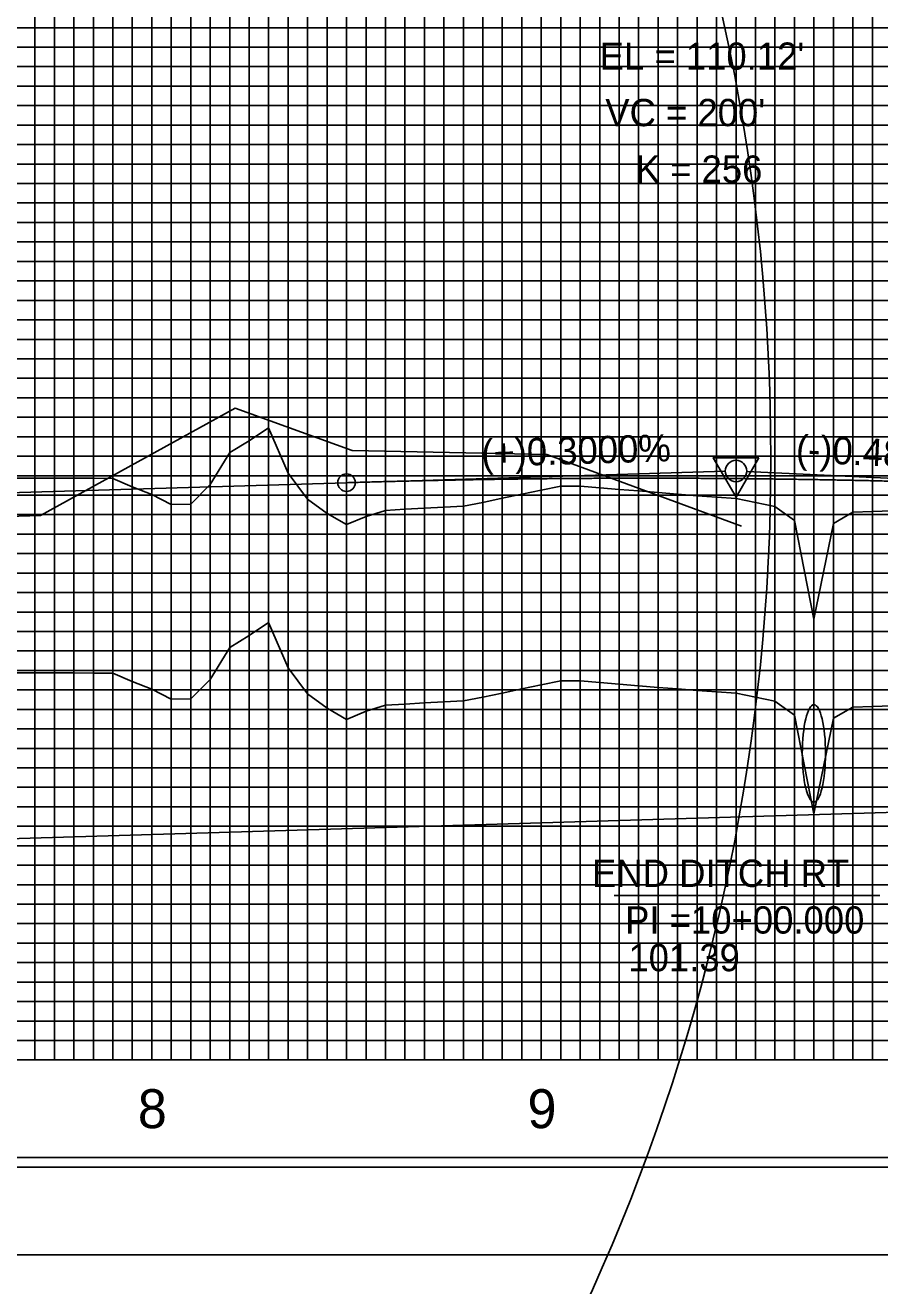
# Model space of a CAD drawing. Extents: x 2345490 to 2445302, y 465165 to 573888.
# Drawn here: x 2411662.8 to 2411882.2, y 527714.1 to 528037.7 of the extents above; entities that cross this region are included whole.
import ezdxf

# ---------------------------------------------------------------- set-up
doc = ezdxf.new("R2010")
doc.units = 0
for name, color, linetype in [('Old_Level_1', 7, 'Continuous'), ('Old_Level_18', 7, 'Continuous'), ('Old_Level_2', 7, 'Continuous'), ('Old_Level_3', 7, 'Continuous'), ('Old_Level_4', 7, 'Continuous'), ('Old_Level_41', 7, 'Continuous'), ('Old_Level_42', 7, 'Continuous'), ('Old_Level_43', 7, 'Continuous'), ('Old_Level_50', 7, 'Continuous'), ('Old_Level_51', 7, 'Continuous'), ('Old_Level_62', 7, 'Continuous'), ('Old_Level_63', 7, 'Continuous')]:
    doc.layers.add(name, color=color, linetype=linetype)

msp = doc.modelspace()

# ---------------------------------------------------------------- linework, layer by layer
at = {"layer": 'Old_Level_1'}
msp.add_lwpolyline([(2411660.325, 527871.39675), (2411665.325, 527871.40325), (2411670.325, 527871.4), (2411675.325, 527871.387), (2411680.325, 527871.364), (2411685.325, 527871.33125), (2411690.325, 527869.2045), (2411695.325, 527867.2145), (2411700.325, 527864.6685), (2411705.325, 527864.74925), (2411710.325, 527869.74075), (2411715.325, 527877.96775), (2411720.325, 527881.0285), (2411725.325, 527884.32975), (2411730.325, 527872.71875), (2411735.325, 527866.0195), (2411740.325, 527862.33025), (2411745.325, 527859.488), (2411750.325, 527861.572), (2411755.325, 527863.093), (2411760.325, 527863.4175), (2411765.325, 527863.7135), (2411770.325, 527863.98125), (2411775.325, 527864.2205), (2411780.325, 527865.149), (2411785.325, 527866.243), (2411790.325, 527867.30725), (2411795.325, 527868.34125), (2411800.325, 527869.3455), (2411805.325, 527869.375), (2411810.325, 527868.94925), (2411815.325, 527868.52725), (2411820.325, 527868.1085), (2411825.325, 527867.6935), (2411830.325, 527867.28175), (2411835.325, 527866.8735), (2411840.325, 527866.55275), (2411845.325, 527866.1855), (2411850.325, 527865.1565), (2411855.325, 527864.12875), (2411860.325, 527860.572), (2411865.325, 527835.20325), (2411870.325, 527859.79525), (2411875.325, 527862.6535), (2411880.325, 527862.82425), (2411885.325, 527862.99775)], dxfattribs=at)
at = {"layer": 'Old_Level_18'}
msp.add_lwpolyline([(2412345.325, 528797.04275), (2410845.325, 528797.04275), (2410845.325, 527747.04275), (2412345.325, 527747.04275)], close=True, dxfattribs=at)
at = {"layer": 'Old_Level_2'}
for p, q in [((2411490.325, 527912.593), (2411745.325, 527920.243)), ((2411745.325, 527920.243), (2411842.57625, 527923.16075)), ((2411945.325, 527918.443), (2411848.072, 527923.11125))]:
    msp.add_line(p, q, dxfattribs=at)
msp.add_lwpolyline([(2411851.19225, 527926.6255), (2411839.44975, 527926.611), (2411845.33325, 527916.49275)], close=True, dxfattribs=at)
for centre, radius in [((2411845.325, 527923.243), 2.75), ((2411745.325, 527920.243), 2.25)]:
    msp.add_circle(centre, radius, dxfattribs=at)
msp.add_spline([(2411745.325, 527920.243), (2411749.325, 527920.36), (2411753.325, 527920.47075), (2411757.325, 527920.575), (2411761.325, 527920.67325), (2411765.325, 527920.765), (2411769.325, 527920.85075), (2411773.325, 527920.93025), (2411777.325, 527921.0035), (2411781.325, 527921.0705), (2411785.325, 527921.131), (2411789.325, 527921.1855), (2411793.325, 527921.23375), (2411797.325, 527921.27575), (2411801.325, 527921.3115), (2411805.325, 527921.341), (2411809.325, 527921.3645), (2411813.325, 527921.3815), (2411817.325, 527921.39225), (2411821.325, 527921.39675), (2411825.325, 527921.395), (2411829.325, 527921.38725), (2411833.325, 527921.373), (2411837.325, 527921.35275), (2411841.325, 527921.326), (2411845.325, 527921.293), (2411849.325, 527921.254), (2411853.325, 527921.20875), (2411857.325, 527921.157), (2411861.325, 527921.09925), (2411865.325, 527921.035), (2411869.325, 527920.96475), (2411873.325, 527920.88825), (2411877.325, 527920.8055), (2411881.325, 527920.7165), (2411885.325, 527920.621), (2411889.325, 527920.5195), (2411893.325, 527920.41175), (2411897.325, 527920.29775), (2411901.325, 527920.1775), (2411905.325, 527920.051), (2411909.325, 527919.9185), (2411913.325, 527919.7795), (2411917.325, 527919.63425), (2411921.325, 527919.48275), (2411925.325, 527919.325), (2411929.325, 527919.16125), (2411933.325, 527918.991), (2411937.325, 527918.81475), (2411941.325, 527918.632), (2411945.325, 527918.443)], degree=3, dxfattribs=at)
at = {"layer": 'Old_Level_3'}
for p, q in [((2411407.325, 527821.24275), (2411895.325, 527835.94275)), ((2411814.00689, 527814.22607), (2411882.22664, 527814.22607))]:
    msp.add_line(p, q, dxfattribs=at)
at = {"layer": 'Old_Level_4'}
msp.add_ellipse((2411865.325, 527850.74275), major_axis=(0, 12.5), ratio=0.238746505, dxfattribs=at)
at = {"layer": 'Old_Level_41'}
msp.add_line((2412345.325, 527772.04275), (2410845.325, 527772.04275), dxfattribs=at)
for points in [[(2411670.325, 528797.04275), (2411670.325, 527772.04275), (2411720.325, 527772.04275), (2411720.325, 528797.04275)], [(2411695.325, 528797.04275), (2411695.325, 527772.04275), (2411745.325, 527772.04275), (2411745.325, 528797.04275)], [(2411770.325, 528797.04275), (2411770.325, 527772.04275), (2411820.325, 527772.04275), (2411820.325, 528797.04275)], [(2411795.325, 528797.04275), (2411795.325, 527772.04275), (2411845.325, 527772.04275), (2411845.325, 528797.04275)], [(2411870.325, 528797.04275), (2411870.325, 527772.04275), (2411920.325, 527772.04275), (2411920.325, 528797.04275)], [(2412345.325, 528022.04275), (2410845.325, 528022.04275), (2410845.325, 528072.04275), (2412345.325, 528072.04275)], [(2412345.325, 527997.04275), (2410845.325, 527997.04275), (2410845.325, 527947.04275), (2412345.325, 527947.04275)], [(2412345.325, 527897.04275), (2410845.325, 527897.04275), (2410845.325, 527847.04275), (2412345.325, 527847.04275)], [(2412345.325, 527822.04275), (2410845.325, 527822.04275), (2410845.325, 527872.04275), (2412345.325, 527872.04275)], [(2412345.325, 527797.04275), (2410845.325, 527797.04275)]]:
    msp.add_lwpolyline(points, dxfattribs=at)
at = {"layer": 'Old_Level_42'}
msp.add_lwpolyline([(2412345.325, 527922.04275), (2410845.325, 527922.04275), (2410845.325, 527972.04275), (2412345.325, 527972.04275)], dxfattribs=at)
at = {"layer": 'Old_Level_43'}
for points in [[(2411665.325, 528797.04275), (2411665.325, 527772.04275), (2411675.325, 527772.04275), (2411675.325, 528797.04275)], [(2411680.325, 528797.04275), (2411680.325, 527772.04275), (2411685.325, 527772.04275), (2411685.325, 528797.04275)], [(2411690.325, 528797.04275), (2411690.325, 527772.04275), (2411700.325, 527772.04275), (2411700.325, 528797.04275)], [(2411705.325, 528797.04275), (2411705.325, 527772.04275), (2411710.325, 527772.04275), (2411710.325, 528797.04275)], [(2411715.325, 528797.04275), (2411715.325, 527772.04275), (2411725.325, 527772.04275), (2411725.325, 528797.04275)], [(2411730.325, 528797.04275), (2411730.325, 527772.04275), (2411735.325, 527772.04275), (2411735.325, 528797.04275)], [(2411740.325, 528797.04275), (2411740.325, 527772.04275), (2411750.325, 527772.04275), (2411750.325, 528797.04275)], [(2411755.325, 528797.04275), (2411755.325, 527772.04275), (2411760.325, 527772.04275), (2411760.325, 528797.04275)], [(2411765.325, 528797.04275), (2411765.325, 527772.04275), (2411775.325, 527772.04275), (2411775.325, 528797.04275)], [(2411780.325, 528797.04275), (2411780.325, 527772.04275), (2411785.325, 527772.04275), (2411785.325, 528797.04275)], [(2411790.325, 528797.04275), (2411790.325, 527772.04275), (2411800.325, 527772.04275), (2411800.325, 528797.04275)], [(2411805.325, 528797.04275), (2411805.325, 527772.04275), (2411810.325, 527772.04275), (2411810.325, 528797.04275)], [(2411815.325, 528797.04275), (2411815.325, 527772.04275), (2411825.325, 527772.04275), (2411825.325, 528797.04275)], [(2411830.325, 528797.04275), (2411830.325, 527772.04275), (2411835.325, 527772.04275), (2411835.325, 528797.04275)], [(2411840.325, 528797.04275), (2411840.325, 527772.04275), (2411850.325, 527772.04275), (2411850.325, 528797.04275)], [(2411855.325, 528797.04275), (2411855.325, 527772.04275), (2411860.325, 527772.04275), (2411860.325, 528797.04275)], [(2411865.325, 528797.04275), (2411865.325, 527772.04275), (2411875.325, 527772.04275), (2411875.325, 528797.04275)], [(2411880.325, 528797.04275), (2411880.325, 527772.04275), (2411885.325, 527772.04275), (2411885.325, 528797.04275)], [(2412295.325, 528037.04275), (2410895.325, 528037.04275), (2410895.325, 528032.04275), (2412295.325, 528032.04275)], [(2412295.325, 528027.04275), (2410895.325, 528027.04275), (2410895.325, 528017.04275), (2412295.325, 528017.04275)], [(2412295.325, 528012.04275), (2410895.325, 528012.04275), (2410895.325, 528007.04275), (2412295.325, 528007.04275)], [(2412295.325, 528002.04275), (2410895.325, 528002.04275), (2410895.325, 527992.04275), (2412295.325, 527992.04275)], [(2412295.325, 527987.04275), (2410895.325, 527987.04275), (2410895.325, 527982.04275), (2412295.325, 527982.04275)], [(2412295.325, 527977.04275), (2410895.325, 527977.04275)], [(2410895.325, 527967.04275), (2412295.325, 527967.04275)], [(2412295.325, 527962.04275), (2410895.325, 527962.04275), (2410895.325, 527957.04275), (2412295.325, 527957.04275)], [(2412295.325, 527952.04275), (2410895.325, 527952.04275)], [(2410895.325, 527942.04275), (2412295.325, 527942.04275)], [(2412295.325, 527937.04275), (2410895.325, 527937.04275), (2410895.325, 527932.04275), (2412295.325, 527932.04275)], [(2412295.325, 527927.04275), (2410895.325, 527927.04275), (2410895.325, 527917.04275), (2412295.325, 527917.04275)], [(2412295.325, 527912.04275), (2410895.325, 527912.04275), (2410895.325, 527907.04275), (2412295.325, 527907.04275)], [(2412295.325, 527902.04275), (2410895.325, 527902.04275), (2410895.325, 527892.04275), (2412295.325, 527892.04275)], [(2412295.325, 527887.04275), (2410895.325, 527887.04275), (2410895.325, 527882.04275), (2412295.325, 527882.04275)], [(2412295.325, 527877.04275), (2410895.325, 527877.04275), (2410895.325, 527867.04275), (2412295.325, 527867.04275)], [(2412295.325, 527862.04275), (2410895.325, 527862.04275), (2410895.325, 527857.04275), (2412295.325, 527857.04275)], [(2412295.325, 527852.04275), (2410895.325, 527852.04275), (2410895.325, 527842.04275), (2412295.325, 527842.04275)], [(2412295.325, 527837.04275), (2410895.325, 527837.04275), (2410895.325, 527832.04275), (2412295.325, 527832.04275)], [(2412295.325, 527827.04275), (2410895.325, 527827.04275), (2410895.325, 527817.04275), (2412295.325, 527817.04275)], [(2412295.325, 527812.04275), (2410895.325, 527812.04275), (2410895.325, 527807.04275), (2412295.325, 527807.04275)], [(2412295.325, 527802.04275), (2410895.325, 527802.04275), (2410895.325, 527792.04275), (2412295.325, 527792.04275)], [(2412295.325, 527787.04275), (2410895.325, 527787.04275), (2410895.325, 527782.04275), (2412295.325, 527782.04275)], [(2412295.325, 527777.04275), (2410895.325, 527777.04275)]]:
    msp.add_lwpolyline(points, dxfattribs=at)
at = {"layer": 'Old_Level_50'}
msp.add_lwpolyline([(2412357.825, 528799.59275), (2410691.325, 528799.59275), (2410691.325, 527744.49275), (2412357.825, 527744.49275)], close=True, dxfattribs=at)
at = {"layer": 'Old_Level_51'}
msp.add_lwpolyline([(2412362.325, 528822.04275), (2410678.325, 528822.04275), (2410678.325, 527722.04275), (2412362.325, 527722.04275)], close=True, dxfattribs=at)
at = {"layer": 'Old_Level_62'}
msp.add_circle((2411335.51705, 527926.51577), 518.74216, dxfattribs=at)
at = {"layer": 'Old_Level_63'}
msp.add_line((2410895.325, 527772.04275), (2413081.64925, 527772.04275), dxfattribs=at)
for points in [[(2410937.46001, 527957.6808), (2410986.64001, 527948.9808), (2411035.83001, 527950.0808), (2411085.01001, 527951.5808), (2411134.21001, 527939.5808), (2411183.43001, 527923.9808), (2411232.67001, 527920.7808), (2411281.95001, 527917.6808), (2411331.27001, 527914.4808), (2411380.65001, 527911.1808), (2411426.73001, 527909.8808), (2411471.73001, 527905.9808), (2411521.73001, 527907.3808), (2411571.73001, 527908.8808), (2411616.73001, 527910.2808), (2411666.73001, 527911.7808), (2411716.73001, 527939.3808), (2411746.73001, 527928.4808), (2411796.73001, 527927.4808), (2411846.73001, 527909.0808)], [(2411660.325, 527921.39675), (2411665.325, 527921.40325), (2411670.325, 527921.4), (2411675.325, 527921.387), (2411680.325, 527921.364), (2411685.325, 527921.33125), (2411690.325, 527919.2045), (2411695.325, 527917.2145), (2411700.325, 527914.6685), (2411705.325, 527914.74925), (2411710.325, 527919.74075), (2411715.325, 527927.96775), (2411720.325, 527931.0285), (2411725.325, 527934.32975), (2411730.325, 527922.71875), (2411735.325, 527916.0195), (2411740.325, 527912.33025), (2411745.325, 527909.488), (2411750.325, 527911.572), (2411755.325, 527913.093), (2411760.325, 527913.4175), (2411765.325, 527913.7135), (2411770.325, 527913.98125), (2411775.325, 527914.2205), (2411780.325, 527915.149), (2411785.325, 527916.243), (2411790.325, 527917.30725), (2411795.325, 527918.34125), (2411800.325, 527919.3455), (2411805.325, 527919.375), (2411810.325, 527918.94925), (2411815.325, 527918.52725), (2411820.325, 527918.1085), (2411825.325, 527917.6935), (2411830.325, 527917.28175), (2411835.325, 527916.8735), (2411840.325, 527916.55275), (2411845.325, 527916.1855), (2411850.325, 527915.1565), (2411855.325, 527914.12875), (2411860.325, 527910.572), (2411865.325, 527885.20325), (2411870.325, 527909.79525), (2411875.325, 527912.6535), (2411880.325, 527912.82425), (2411885.325, 527912.99775)]]:
    msp.add_lwpolyline(points, dxfattribs=at)

# ---------------------------------------------------------------- texts
at = {"layer": 'Old_Level_2'}
for s, height, p in [("EL = 110.12'", 7.0000005, (2411810.325, 528026.243)), ("VC = 200'", 7.000001, (2411811.74925, 528011.76325)), ('K = 256', 7.000001, (2411819.56825, 527997.23675))]:
    msp.add_text(s, height=height, dxfattribs=at).set_placement(p)
for s, rotation, p in [('(+)0.3000%', 1.7183583, (2411780.025, 527924.28575)), ('(-)0.4800%', 357.2519111, (2411860.5975, 527925.5135))]:
    msp.add_text(s, height=7.000001, rotation=rotation, dxfattribs=at).set_placement(p)
at = {"layer": 'Old_Level_3'}
for s, height, p in [('END DITCH RT', 7.0000005, (2411808.35929, 527816.46896)), ('PI =10+00.000', 7.0000005, (2411816.85027, 527804.48586)), ('101.39', 7.000001, (2411817.68882, 527794.81533))]:
    msp.add_text(s, height=height, rotation=360, dxfattribs=at).set_placement(p)
at = {"layer": 'Old_Level_62'}
for s, p in [('8', (2411691.748, 527754.543)), ('9', (2411791.79025, 527754.543))]:
    msp.add_text(s, height=10, dxfattribs=at).set_placement(p)

doc.saveas('drawing.dxf')
